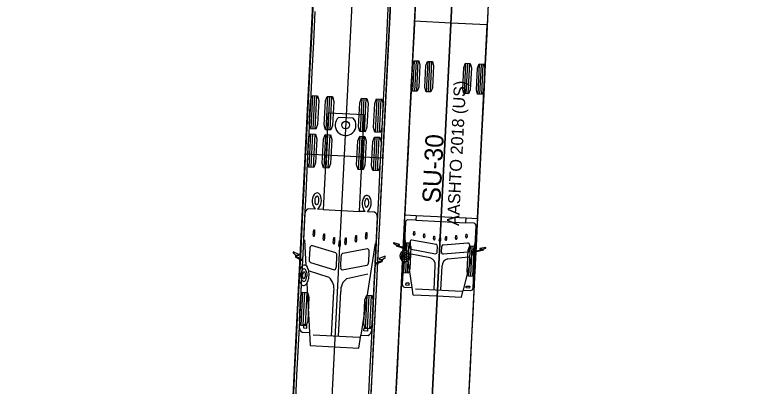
# Model space of a CAD drawing. Extents: x 260275 to 261282, y 610916 to 614143.
# Drawn here: x 260986.2 to 261067.3, y 611831.5 to 611872.3 of the extents above; entities that cross this region are included whole.
import ezdxf

# ---------------------------------------------------------------- set-up
doc = ezdxf.new("R2010")
doc.units = 0
doc.layers.add('GE_X_Alignment', color=7, linetype='Continuous')
doc.layers.add('UT_X_Water_Cells', color=7, linetype='Continuous')

msp = doc.modelspace()

# ---------------------------------------------------------------- linework, layer by layer
at = {"layer": 'GE_X_Alignment'}
msp.add_line((260986.249, 610915.954), (261148.276, 614142.838), dxfattribs=at)
at = {"layer": 'UT_X_Water_Cells'}
for p, q in [((261044.031, 612066.726), (261023.69, 611661.632)), ((261031.95, 612045.486), (261010.925, 611626.741)), ((261030.049, 611863.873), (261030.216, 611867.202)), ((261030.257, 611863.862), (261030.424, 611867.191)), ((261030.465, 611863.852), (261030.632, 611867.181)), ((261031.547, 611863.797), (261031.714, 611867.127)), ((261031.755, 611863.787), (261031.922, 611867.116)), ((261031.963, 611863.777), (261032.13, 611867.106)), ((261035.708, 611863.588), (261035.876, 611866.918)), ((261035.916, 611863.578), (261036.084, 611866.907)), ((261036.124, 611863.568), (261036.292, 611866.897)), ((261037.206, 611863.513), (261037.374, 611866.842)), ((261037.415, 611863.503), (261037.582, 611866.832)), ((261037.623, 611863.492), (261037.79, 611866.822)), ((261018.847, 611859.706), (261019.03, 611863.368)), ((261019.075, 611859.695), (261019.259, 611863.357)), ((261019.304, 611859.683), (261019.488, 611863.345)), ((261020.495, 611859.623), (261020.678, 611863.285)), ((261020.723, 611859.612), (261020.907, 611863.274)), ((261020.952, 611859.6), (261021.136, 611863.262)), ((261024.273, 611859.434), (261024.457, 611863.096)), ((261024.502, 611859.422), (261024.686, 611863.084)), ((261024.731, 611859.411), (261024.915, 611863.073)), ((261025.921, 611859.351), (261026.105, 611863.013)), ((261026.15, 611859.339), (261026.334, 611863.001)), ((261026.379, 611859.328), (261026.563, 611862.99)), ((261023.491, 611860.904), (261021.877, 611860.985)), ((261018.636, 611855.511), (261018.82, 611859.173)), ((261018.865, 611855.5), (261019.049, 611859.162)), ((261019.094, 611855.488), (261019.278, 611859.15)), ((261020.284, 611855.429), (261020.468, 611859.091)), ((261020.513, 611855.417), (261020.697, 611859.079)), ((261020.742, 611855.406), (261020.926, 611859.068)), ((261024.062, 611855.239), (261024.246, 611858.901)), ((261024.291, 611855.227), (261024.475, 611858.889)), ((261024.52, 611855.216), (261024.704, 611858.878)), ((261025.71, 611855.156), (261025.894, 611858.818)), ((261025.939, 611855.145), (261026.123, 611858.807)), ((261026.168, 611855.133), (261026.352, 611858.795)), ((261019.302, 611850.905), (261018.528, 611850.944)), ((261020.189, 611850.861), (261024.157, 611850.662)), ((261025.818, 611850.578), (261025.044, 611850.617)), ((261030.41, 611850.217), (261035.895, 611849.942)), ((261030.384, 611849.687), (261035.869, 611849.411)), ((261019.075, 611848.09), (261019.139, 611848.637)), ((261019.139, 611848.637), (261019.221, 611848.633)), ((261019.221, 611848.633), (261019.23, 611848.083)), ((261020.172, 611847.649), (261020.235, 611848.196)), ((261020.235, 611848.196), (261020.318, 611848.192)), ((261020.318, 611848.192), (261020.326, 611847.641)), ((261024.833, 611847.801), (261024.897, 611848.348)), ((261024.897, 611848.348), (261024.979, 611848.344)), ((261024.979, 611848.344), (261024.988, 611847.793)), ((261030.093, 611848.159), (261030.144, 611848.457)), ((261030.144, 611848.457), (261030.226, 611848.453)), ((261030.226, 611848.453), (261030.247, 611848.152)), ((261031.198, 611847.893), (261031.249, 611848.191)), ((261031.249, 611848.191), (261031.331, 611848.187)), ((261031.331, 611848.187), (261031.352, 611847.886)), ((261035.851, 611847.87), (261035.902, 611848.168)), ((261035.902, 611848.168), (261035.984, 611848.164)), ((261035.984, 611848.164), (261036.005, 611847.863)), ((261018.106, 611847.522), (261018.258, 611844.723)), ((261021.271, 611847.259), (261021.334, 611847.806)), ((261021.334, 611847.806), (261021.417, 611847.802)), ((261021.417, 611847.802), (261021.425, 611847.252)), ((261021.903, 611846.919), (261021.966, 611847.466)), ((261021.966, 611847.466), (261022.049, 611847.462)), ((261022.049, 611847.462), (261022.057, 611846.911)), ((261022.566, 611847.194), (261022.629, 611847.741)), ((261022.629, 611847.741), (261022.712, 611847.737)), ((261022.712, 611847.737), (261022.72, 611847.187)), ((261023.698, 611847.447), (261023.762, 611848.019)), ((261023.762, 611848.019), (261023.844, 611848.015)), ((261023.844, 611848.015), (261023.852, 611847.439)), ((261029.137, 611847.871), (261029.353, 611846.337)), ((261029.745, 611847.321), (261029.714, 611846.705)), ((261032.61, 611847.027), (261029.936, 611847.514)), ((261032.305, 611847.655), (261032.356, 611847.953)), ((261032.356, 611847.953), (261032.438, 611847.949)), ((261032.438, 611847.949), (261032.459, 611847.647)), ((261032.944, 611847.455), (261032.995, 611847.752)), ((261032.995, 611847.752), (261033.077, 611847.748)), ((261033.077, 611847.748), (261033.098, 611847.447)), ((261033.599, 611847.59), (261033.65, 611847.888)), ((261033.65, 611847.888), (261033.733, 611847.884)), ((261033.733, 611847.884), (261033.754, 611847.582)), ((261034.725, 611847.703), (261034.775, 611848.014)), ((261034.775, 611848.014), (261034.858, 611848.01)), ((261034.858, 611848.01), (261034.879, 611847.695)), ((261036.927, 611847.48), (261035.586, 611842.012)), ((261018.692, 611846.54), (261018.635, 611845.411)), ((261021.55, 611846.122), (261018.892, 611846.901)), ((261022.328, 611846.083), (261025.051, 611846.592)), ((261025.896, 611847.131), (261024.324, 611837.063)), ((261029.046, 611843.898), (261029.213, 611847.227)), ((261029.254, 611843.887), (261029.421, 611847.217)), ((261029.462, 611843.877), (261029.629, 611847.206)), ((261029.855, 611846.496), (261032.528, 611846.009)), ((261032.72, 611846.202), (261032.751, 611846.818)), ((261033.195, 611846.178), (261033.226, 611846.794)), ((261033.387, 611846.988), (261036.096, 611847.204)), ((261036.203, 611843.538), (261036.371, 611846.868)), ((261036.267, 611846.993), (261036.236, 611846.378)), ((261036.412, 611843.528), (261036.579, 611846.857)), ((261036.62, 611843.518), (261036.787, 611846.847)), ((261017.16, 611845.841), (261017.14, 611845.858)), ((261017.186, 611845.841), (261017.16, 611845.841)), ((261021.626, 611844.616), (261021.683, 611845.745)), ((261022.101, 611844.592), (261022.158, 611845.721)), ((261025.214, 611846.213), (261025.157, 611845.084)), ((261031.943, 611845.552), (261029.687, 611846.012)), ((261036.075, 611846.183), (261033.366, 611845.967)), ((261033.903, 611845.453), (261036.182, 611845.684)), ((261018.768, 611845.034), (261021.426, 611844.255)), ((261026.642, 611845.366), (261026.668, 611845.363)), ((261026.668, 611845.363), (261026.689, 611845.379)), ((261029.001, 611845.172), (261028.875, 611842.653)), ((261029.505, 611845.262), (261029.923, 611842.297)), ((261020.82, 611843.392), (261018.579, 611844.142)), ((261024.987, 611844.721), (261022.264, 611844.213)), ((261032.366, 611842.051), (261032.5, 611844.716)), ((261033.131, 611842.013), (261033.265, 611844.677)), ((261022.781, 611843.294), (261025.074, 611843.812)), ((261017.761, 611842.657), (261017.525, 611837.963)), ((261018.365, 611842.761), (261018.661, 611837.347)), ((261029.258, 611842.786), (261029.248, 611842.592)), ((261029.248, 611842.592), (261029.626, 611842.574)), ((261029.636, 611842.767), (261029.258, 611842.786)), ((261029.626, 611842.574), (261029.636, 611842.767)), ((261035.91, 611842.258), (261035.919, 611842.452)), ((261035.919, 611842.452), (261036.298, 611842.433)), ((261036.298, 611842.433), (261036.288, 611842.239)), ((261017.763, 611838.133), (261017.947, 611841.795)), ((261017.992, 611838.122), (261018.176, 611841.784)), ((261018.221, 611838.11), (261018.405, 611841.772)), ((261021.099, 611836.999), (261021.344, 611841.885)), ((261021.863, 611836.961), (261022.109, 611841.846)), ((261030.332, 611842.153), (261035.431, 611841.897)), ((261036.288, 611842.239), (261035.91, 611842.258)), ((261024.838, 611837.778), (261025.022, 611841.44)), ((261025.067, 611837.766), (261025.251, 611841.429)), ((261025.296, 611837.755), (261025.479, 611841.417)), ((261018.014, 611838.216), (261017.996, 611837.861)), ((261017.996, 611837.861), (261018.375, 611837.842)), ((261018.392, 611838.197), (261018.014, 611838.216)), ((261018.375, 611837.842), (261018.392, 611838.197)), ((261024.658, 611837.526), (261024.676, 611837.882)), ((261024.676, 611837.882), (261025.054, 611837.863)), ((261025.054, 611837.863), (261025.036, 611837.507)), ((261019.065, 611837.101), (261024.163, 611836.845)), ((261025.036, 611837.507), (261024.658, 611837.526)), ((261018.739, 611835.915), (261024.103, 611835.645))]:
    msp.add_line(p, q, dxfattribs=at)
for points in [[(261009.34, 611680.102), (261030.965, 612110.617), (261039.455, 612110.191), (261039.447, 612110.045), (261039.447, 612110.045)], [(261039.447, 612110.045), (261018.12, 611685.301)], [(261020.965, 611687.133), (261041.34, 612092.893), (261049.33, 612092.492), (261049.322, 612092.345), (261049.322, 612092.345)], [(261049.322, 612092.345), (261028.546, 611678.469)], [(261020.655, 611904.835), (261020.633, 611904.836), (261018.229, 611856.967), (261022.474, 611856.754), (261026.719, 611856.541), (261029.122, 611904.41), (261029.1, 611904.411)], [(261027.421, 611875.524), (261027.254, 611872.195), (261027.087, 611868.867), (261026.92, 611865.538), (261026.753, 611862.209), (261026.586, 611858.881), (261026.419, 611855.552), (261026.252, 611852.223), (261026.084, 611848.895), (261025.917, 611845.566), (261025.75, 611842.237), (261025.583, 611838.909), (261025.416, 611835.58), (261025.249, 611832.252), (261025.082, 611828.923)], [(261030.342, 611873.869), (261030.175, 611870.541), (261030.008, 611867.212), (261029.841, 611863.883), (261029.674, 611860.555), (261029.506, 611857.226), (261029.339, 611853.898), (261029.172, 611850.569), (261029.005, 611847.24), (261028.838, 611843.912), (261028.671, 611840.583), (261028.504, 611837.254), (261028.337, 611833.926), (261028.169, 611830.597)], [(261030.342, 611873.866), (261030.175, 611870.538), (261030.008, 611867.209), (261029.841, 611863.88), (261029.673, 611860.552), (261029.506, 611857.223), (261029.339, 611853.894), (261029.172, 611850.566), (261029.005, 611847.237), (261028.838, 611843.909), (261028.671, 611840.58), (261028.504, 611837.251), (261028.336, 611833.923), (261028.169, 611830.594)], [(261038.332, 611873.468), (261038.165, 611870.139), (261037.998, 611866.811), (261037.831, 611863.482), (261037.664, 611860.154), (261037.496, 611856.825), (261037.329, 611853.496), (261037.162, 611850.168), (261036.995, 611846.839), (261036.828, 611843.51), (261036.661, 611840.182), (261036.494, 611836.853), (261036.326, 611833.525), (261036.159, 611830.196)], [(261038.332, 611873.465), (261038.165, 611870.136), (261037.998, 611866.808), (261037.831, 611863.479), (261037.663, 611860.15), (261037.496, 611856.822), (261037.329, 611853.493), (261037.162, 611850.165), (261036.995, 611846.836), (261036.828, 611843.507), (261036.661, 611840.179), (261036.493, 611836.85), (261036.326, 611833.521), (261036.159, 611830.193)], [(261019.04, 611873.117), (261018.873, 611869.789), (261018.706, 611866.46), (261018.539, 611863.131), (261018.372, 611859.803), (261018.205, 611856.474), (261018.037, 611853.145), (261017.87, 611849.817), (261017.703, 611846.488), (261017.536, 611843.159), (261017.369, 611839.831), (261017.202, 611836.502), (261017.035, 611833.173), (261016.867, 611829.845)], [(261019.264, 611872.597), (261019.097, 611869.268), (261018.93, 611865.939), (261018.763, 611862.611), (261018.596, 611859.282), (261018.429, 611855.953), (261018.262, 611852.625), (261018.094, 611849.296), (261017.927, 611845.967), (261017.76, 611842.639), (261017.593, 611839.31), (261017.426, 611835.981), (261017.259, 611832.653), (261017.092, 611829.324)], [(261027.53, 611872.691), (261027.362, 611869.362), (261027.195, 611866.034), (261027.028, 611862.705), (261026.861, 611859.376), (261026.694, 611856.048), (261026.527, 611852.719), (261026.36, 611849.39), (261026.192, 611846.062), (261026.025, 611842.733), (261025.858, 611839.404), (261025.691, 611836.076), (261025.524, 611832.747), (261025.357, 611829.418)], [(261036.767, 611849.366), (261035.872, 611849.411), (261035.869, 611849.415), (261035.895, 611849.941), (261035.906, 611849.942), (261037.148, 611849.879), (261038.215, 611871.139), (261034.22, 611871.34), (261030.225, 611871.54), (261029.158, 611850.28), (261030.399, 611850.218), (261030.41, 611850.217), (261030.384, 611849.69), (261030.38, 611849.687), (261029.485, 611849.732)], [(261024.787, 611850.63), (261024.157, 611850.662), (261024.689, 611861.248), (261020.72, 611861.448), (261020.189, 611850.861), (261019.559, 611850.893)], [(261018.15, 611850.405), (261017.895, 611845.33), (261017.192, 611845.721), (261017.192, 611845.721)], [(261026.624, 611845.248), (261026.624, 611845.248), (261025.885, 611844.928), (261026.14, 611850.004)], [(261029.215, 611849.429), (261029.076, 611846.659), (261029.071, 611846.647), (261028.265, 611846.907), (261028.265, 611846.907)], [(261037.698, 611846.434), (261037.698, 611846.434), (261036.87, 611846.255), (261036.866, 611846.268), (261037.005, 611849.038)], [(261028.255, 611846.928), (261028.257, 611846.972), (261028.257, 611846.973), (261028.575, 611846.965), (261028.577, 611846.965), (261028.58, 611847.021), (261028.577, 611847.022), (261027.929, 611847.194), (261027.926, 611847.195), (261027.923, 611847.13), (261028.211, 611846.983), (261028.211, 611846.983), (261028.209, 611846.936)], [(261028.246, 611846.861), (261028.247, 611846.861), (261029.066, 611846.593), (261029.072, 611846.581), (261029.061, 611846.353)], [(261037.756, 611846.456), (261037.76, 611846.503), (261037.76, 611846.504), (261038.061, 611846.621), (261038.064, 611846.686), (261038.061, 611846.685), (261037.399, 611846.579), (261037.396, 611846.578), (261037.393, 611846.523), (261037.396, 611846.522), (261037.713, 611846.498), (261037.713, 611846.497), (261037.71, 611846.453)], [(261017.182, 611845.759), (261017.186, 611845.841), (261017.507, 611845.84), (261017.512, 611845.943), (261016.864, 611846.234), (261016.858, 611846.114), (261017.14, 611845.858), (261017.137, 611845.771)], [(261026.684, 611845.292), (261026.689, 611845.379), (261026.996, 611845.605), (261027.002, 611845.725), (261026.328, 611845.501), (261026.323, 611845.398), (261026.642, 611845.366), (261026.638, 611845.284)], [(261036.665, 611842.262), (261036.862, 611846.19), (261036.87, 611846.201), (261037.711, 611846.386), (261037.712, 611846.386)], [(261017.171, 611845.636), (261017.89, 611845.23), (261017.862, 611844.658)], [(261025.515, 611837.561), (261025.88, 611844.829), (261026.637, 611845.16)], [(261029.113, 611842.337), (261029.919, 611842.297), (261029.924, 611842.292), (261030.033, 611841.514), (261030.075, 611841.51), (261032.716, 611841.377), (261035.356, 611841.245), (261035.398, 611841.245), (261035.585, 611842.008), (261035.59, 611842.012), (261036.397, 611841.972)], [(261017.847, 611837.388), (261018.661, 611837.347), (261018.738, 611835.927)], [(261018.739, 611835.915), (261024.103, 611835.645), (261024.324, 611837.063), (261025.138, 611837.022)]]:
    msp.add_lwpolyline(points, dxfattribs=at)
for points in [[(261030.517, 611863.849), (261029.997, 611863.875), (261029.864, 611864.349), (261029.984, 611866.746), (261030.164, 611867.204), (261030.684, 611867.178), (261030.817, 611866.704), (261030.696, 611864.307)], [(261032.015, 611863.774), (261031.495, 611863.8), (261031.362, 611864.274), (261031.483, 611866.671), (261031.662, 611867.129), (261032.182, 611867.103), (261032.315, 611866.629), (261032.195, 611864.232)], [(261036.176, 611863.565), (261035.657, 611863.591), (261035.524, 611864.065), (261035.644, 611866.462), (261035.824, 611866.92), (261036.343, 611866.894), (261036.476, 611866.42), (261036.356, 611864.023)], [(261037.674, 611863.49), (261037.155, 611863.516), (261037.022, 611863.99), (261037.142, 611866.387), (261037.322, 611866.845), (261037.841, 611866.819), (261037.974, 611866.345), (261037.854, 611863.948)], [(261019.361, 611859.68), (261018.79, 611859.709), (261018.643, 611860.23), (261018.776, 611862.867), (261018.974, 611863.371), (261019.545, 611863.342), (261019.691, 611862.821), (261019.559, 611860.184)], [(261021.009, 611859.597), (261020.438, 611859.626), (261020.291, 611860.147), (261020.424, 611862.784), (261020.622, 611863.288), (261021.193, 611863.259), (261021.339, 611862.738), (261021.207, 611860.101)], [(261024.788, 611859.408), (261024.216, 611859.436), (261024.07, 611859.958), (261024.202, 611862.594), (261024.4, 611863.098), (261024.971, 611863.07), (261025.118, 611862.548), (261024.985, 611859.912)], [(261026.436, 611859.325), (261025.864, 611859.354), (261025.718, 611859.875), (261025.85, 611862.512), (261026.048, 611863.016), (261026.619, 611862.987), (261026.766, 611862.466), (261026.633, 611859.829)], [(261019.15, 611855.485), (261018.579, 611855.514), (261018.433, 611856.035), (261018.565, 611858.672), (261018.763, 611859.176), (261019.334, 611859.148), (261019.481, 611858.626), (261019.348, 611855.99)], [(261020.798, 611855.403), (261020.227, 611855.431), (261020.081, 611855.953), (261020.213, 611858.589), (261020.411, 611859.093), (261020.982, 611859.065), (261021.129, 611858.543), (261020.996, 611855.907)], [(261024.577, 611855.213), (261024.006, 611855.242), (261023.859, 611855.763), (261023.992, 611858.4), (261024.19, 611858.904), (261024.761, 611858.875), (261024.907, 611858.354), (261024.775, 611855.717)], [(261026.225, 611855.13), (261025.654, 611855.159), (261025.507, 611855.68), (261025.64, 611858.317), (261025.838, 611858.821), (261026.409, 611858.792), (261026.555, 611858.271), (261026.423, 611855.634)], [(261029.514, 611843.874), (261028.994, 611843.9), (261028.861, 611844.374), (261028.982, 611846.771), (261029.161, 611847.23), (261029.681, 611847.203), (261029.814, 611846.73), (261029.693, 611844.333)], [(261036.671, 611843.515), (261036.152, 611843.541), (261036.019, 611844.015), (261036.139, 611846.412), (261036.319, 611846.87), (261036.838, 611846.844), (261036.971, 611846.37), (261036.851, 611843.973)], [(261018.278, 611838.107), (261017.707, 611838.136), (261017.56, 611838.657), (261017.693, 611841.294), (261017.891, 611841.798), (261018.462, 611841.769), (261018.608, 611841.248), (261018.476, 611838.611)], [(261025.352, 611837.752), (261024.781, 611837.781), (261024.635, 611838.302), (261024.767, 611840.939), (261024.965, 611841.443), (261025.536, 611841.414), (261025.683, 611840.893), (261025.55, 611838.256)]]:
    msp.add_lwpolyline(points, close=True, dxfattribs=at)
for centre, radius in [((261022.644, 611860.138), 0.424), ((261029.176, 611845.755), 0.374), ((261029.176, 611845.755), 0.193)]:
    msp.add_circle(centre, radius, dxfattribs=at)
for centre, radius, start, end in [((261022.644, 611860.138), 1.143, 132.1255, 42.1255), ((261020.315, 611851.788), 1.344, 147.53526, 221.09006), ((261019.501, 611852.299), 0.383, 27.59628, 146.65472), ((261020.103, 611851.839), 0.86, 155.59014, 195.55953), ((261019.534, 611852.116), 0.228, 97.92836, 159.8232), ((261019.428, 611852.09), 0.262, 6.80834, 73.33353), ((261018.64, 611851.873), 1.344, 313.16094, 26.71574), ((261025.8, 611851.513), 1.344, 147.53526, 221.09006), ((261024.985, 611852.016), 0.387, 28.62104, 145.62996), ((261024.125, 611851.597), 1.344, 313.16094, 26.71574), ((261019.558, 611851.675), 0.29, 193.32121, 249.48124), ((261019.418, 611851.648), 0.247, 278.8428, 348.7219), ((261018.836, 611851.905), 0.879, 339.66236, 14.25761), ((261025.608, 611851.565), 0.879, 159.9934, 194.58864), ((261025.003, 611851.367), 0.247, 185.52911, 255.4082), ((261025.038, 611851.809), 0.262, 100.91747, 167.44267), ((261024.934, 611851.845), 0.228, 14.4278, 76.32264), ((261024.34, 611851.626), 0.86, 338.69148, 18.66086), ((261018.721, 611850.407), 0.571, 109.81853, 180.21012), ((261024.867, 611851.409), 0.29, 284.76976, 340.92979), ((261025.572, 611850.063), 0.571, 354.04089, 64.43248), ((261029.537, 611849.413), 0.323, 99.2771, 177.1255), ((261036.683, 611849.054), 0.323, 357.1255, 74.97391), ((261019.261, 611848.039), 0.192, 164.57524, 232.04981), ((261019.04, 611848.05), 0.192, 302.17384, 9.70311), ((261030.181, 611848.137), 0.091, 165.44206, 259.60593), ((261030.157, 611848.138), 0.0909, 274.60942, 8.84462), ((261020.357, 611847.598), 0.192, 164.57524, 232.04981), ((261020.137, 611847.609), 0.192, 302.17384, 9.70311), ((261023.883, 611847.421), 0.192, 164.5479, 232.07716), ((261023.663, 611847.432), 0.192, 302.20119, 9.67576), ((261025.019, 611847.75), 0.192, 164.5479, 232.07716), ((261024.798, 611847.761), 0.192, 302.20119, 9.67576), ((261029.929, 611847.329), 0.184, 87.71808, 182.58934), ((261031.286, 611847.87), 0.091, 165.44206, 259.60593), ((261031.262, 611847.872), 0.0909, 274.60942, 8.84462), ((261032.393, 611847.632), 0.091, 165.44206, 259.60593), ((261032.369, 611847.633), 0.0909, 274.60942, 8.84462), ((261033.032, 611847.432), 0.091, 165.44206, 259.60593), ((261033.008, 611847.433), 0.091, 274.64508, 8.80895), ((261033.687, 611847.567), 0.0909, 165.40639, 259.64159), ((261033.664, 611847.569), 0.091, 274.64508, 8.80895), ((261034.812, 611847.693), 0.0909, 165.40639, 259.64159), ((261034.789, 611847.695), 0.091, 274.64508, 8.80895), ((261035.939, 611847.847), 0.0909, 165.40639, 259.64159), ((261035.915, 611847.849), 0.091, 274.64508, 8.80895), ((261019.024, 611846.595), 0.334, 113.39037, 185.98833), ((261021.456, 611847.208), 0.192, 164.57524, 232.04981), ((261021.236, 611847.219), 0.192, 302.17384, 9.70311), ((261022.088, 611846.867), 0.192, 164.57524, 232.04981), ((261021.867, 611846.879), 0.192, 302.20119, 9.67576), ((261022.751, 611847.143), 0.192, 164.5479, 232.07716), ((261022.53, 611847.154), 0.192, 302.20119, 9.67576), ((261024.889, 611846.3), 0.334, 348.26267, 60.86063), ((261028.228, 611846.899), 0.0418, 117.61865, 294.63358), ((261028.223, 611846.899), 0.0434, 11.03902, 41.7118), ((261029.905, 611846.682), 0.193, 173.06859, 254.98308), ((261032.56, 611846.841), 0.193, 353.06366, 74.98801), ((261033.418, 611846.798), 0.193, 99.26299, 181.18734), ((261036.085, 611847.02), 0.184, 351.66167, 86.53293), ((261037.733, 611846.422), 0.0418, 239.61742, 56.63235), ((261017.241, 611845.698), 0.127, 145.02093, 209.23008), ((261017.082, 611845.714), 0.11, 4.06966, 24.17798), ((261021.292, 611845.821), 0.397, 351.20134, 49.36435), ((261022.555, 611845.757), 0.397, 124.88665, 183.04966), ((261029.243, 611845.752), 0.628, 106.8788, 247.3705), ((261029.18, 611845.842), 0.524, 49.38452, 103.18459), ((261029.107, 611845.75), 0.629, 309.17109, 357.86038), ((261029.107, 611845.766), 0.63, 356.4803, 48.88311), ((261032.536, 611846.194), 0.184, 267.72364, 2.58377), ((261033.377, 611846.151), 0.184, 171.66723, 266.52737), ((261036.044, 611846.374), 0.193, 279.26792, 1.18241), ((261037.739, 611846.421), 0.0434, 132.53921, 163.21198), ((261017.151, 611845.649), 0.0244, 212.94354, 326.25791), ((261019.032, 611845.339), 0.403, 169.66784, 229.12579), ((261024.755, 611845.051), 0.403, 305.12521, 4.58316), ((261026.733, 611845.229), 0.11, 150.07302, 170.18134), ((261026.658, 611845.172), 0.0244, 207.99309, 321.30746), ((261026.573, 611845.229), 0.127, 325.02093, 29.23008), ((261029.172, 611845.669), 0.526, 251.07067, 309.31667), ((261031.733, 611844.808), 0.773, 353.15088, 74.23504), ((261034.037, 611844.692), 0.773, 100.01597, 181.10013), ((261019.697, 611843.563), 2.204, 164.32456, 183.95974), ((261018.48, 611843.971), 0.924, 132.02262, 168.30076), ((261018.627, 611843.677), 0.913, 140.43513, 180.69541), ((261018.096, 611844.469), 0.301, 57.35677, 141.25506), ((261018.079, 611844.135), 0.199, 40.92879, 141.5681), ((261017.49, 611843.728), 0.914, 353.95993, 36.01791), ((261017.769, 611844.092), 0.799, 12.92493, 52.19257), ((261016.608, 611843.734), 2.012, 356.76687, 15.44978), ((261021.285, 611844.563), 0.342, 295.59721, 5.52369), ((261022.436, 611844.505), 0.342, 168.72731, 238.65379), ((261019.226, 611843.517), 1.731, 183.5106, 198.70836), ((261018.946, 611843.596), 1.234, 176.75519, 194.33734), ((261018.153, 611843.35), 0.407, 188.35614, 251.16055), ((261018.51, 611843.621), 0.631, 150.93378, 193.73431), ((261018.114, 611843.502), 0.22, 188.13535, 249.83363), ((261018.069, 611843.882), 0.12, 12.10162, 157.57965), ((261017.954, 611843.552), 0.27, 288.27444, 1.01824), ((261017.617, 611843.67), 0.617, 349.4131, 22.60389), ((261017.301, 611843.665), 1.098, 330.39127, 358.28386), ((261016.57, 611843.713), 2.049, 341.50654, 357.43184), ((261019.739, 611842.172), 1.631, 349.85894, 48.44967), ((261023.735, 611841.971), 1.631, 125.80134, 184.39207), ((261018.279, 611843.156), 0.719, 195.6559, 223.91288), ((261018.022, 611842.856), 0.328, 217.21385, 266.11819), ((261017.997, 611842.908), 0.38, 270.45588, 320.97941), ((261018.012, 611843.232), 0.268, 272.19814, 335.87577), ((261017.487, 611843.379), 1.074, 318.58211, 342.85096), ((261029.154, 611842.616), 0.282, 172.49767, 261.5771), ((261036.384, 611842.253), 0.282, 272.67391, 1.75333), ((261018.314, 611838.027), 0.792, 184.65895, 233.81442), ((261024.737, 611837.704), 0.792, 300.43659, 349.59206)]:
    msp.add_arc(centre, radius, start, end, dxfattribs=at)
for centre, major_axis, start_param, end_param in [((261017.153, 611845.702), (-0.0039, -0.0781), 2.398717, 3.668019), ((261017.153, 611845.702), (0.0039, 0.0781), 3.71124, 4.981984), ((261026.661, 611845.225), (-0.0039, -0.0781), 4.442794, 5.713538), ((261026.661, 611845.225), (0.0039, 0.0781), 5.756759, 7.026061)]:
    msp.add_ellipse(centre, major_axis=major_axis, ratio=0.5, start_param=start_param, end_param=end_param, dxfattribs=at)

# ---------------------------------------------------------------- texts
for s, height, p in [('AASHTO 2018 (US)', 1.33333, (261035.11, 611849.053)), ('SU-30', 2, (261033.065, 611851.515))]:
    msp.add_text(s, height=height, rotation=87.1255, dxfattribs=at).set_placement(p)

doc.saveas('drawing.dxf')
